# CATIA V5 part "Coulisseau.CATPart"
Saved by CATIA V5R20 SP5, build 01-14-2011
Part number: Coulisseau
Publications: "Longueur coulisseau", "Diamètre coulisseau", "Corps principal"
Bounding box of the stored display mesh (mm): x -5 to 12, y 37.949 to 47.949, z -5 to 16
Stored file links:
  C:\Documents and Settings\pschann\Bureau\IAO\Coulisseau.CATPart
  C:\Documents and Settings\pschann\Bureau\IAO\pschann.CATProduct
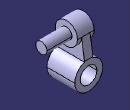
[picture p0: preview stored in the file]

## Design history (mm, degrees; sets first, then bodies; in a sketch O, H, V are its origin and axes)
Parameters
  `Longueur coulisseau` = 10 mm
  `Diamètre coulisseau` = 10 mm
External parameters (linked from other documents)
  `External.Diamètre pivot` = 4 mm
  `External.Epaisseur pivot` = 2 mm
  `External.Longueur axe pivot` = 6 mm
Set1
  Sketch1 on yz-plane, origin (0, 0, 0), H (0, 1, 0), V (0, 0, 1)
    circle A1 centre (42.9491, 12) radius 4
    point P1 (42.9491, 12)
    reference projected point E1 (42.9491, 12) from Point1
    radius A1 = 4 {= `External.Diamètre pivot` /2+`External.Epaisseur pivot`}
    coincidence: P1 E1
Set2
  Point1 "C": linked copy from another document
  Point2 "A": linked copy from another document
  Point3: linked copy from another document
  Line1: linked copy from another document
Body1 (main body)
  Pad1: profile Sketch1, direction (1, 0, 0), length 3 {= `External.Longueur axe pivot` /2}, mirrored extent
  Sketch2 on end face of Pad1, origin (3, 0, 0), H (0, 1, 0), V (0, 0, 1)
    circle A1 centre (42.9491, 12) radius 2
    reference projected point E1 (42.9491, 12) from Point1
    radius A1 = 2 {= `External.Diamètre pivot` /2}
    concentricity: A1 E1
  Pad2: profile Sketch2, direction (1, 0, 0), length 9 {= `External.Longueur axe pivot` *1.5}
  Sketch3 on yz-plane, origin (0, 0, 0), H (0, 1, 0), V (0, 0, 1)
    line L1 (38.9491, 12) -> (37.9491, 5)
    point P1 (38.9491, 12)
    line L2 (37.9491, 5) -> (37.9491, 0)
    line L3 (37.9491, 0) -> (47.9491, 0)
    line L4 (47.9491, 5) -> (47.9491, 0)
    line L5 (47.9491, 5) -> (46.9491, 12)
    point P6 (46.9491, 12)
    line L6 (46.9491, 12) -> (38.9491, 12)
    reference projected point E1 (42.9491, 12) from Point1
    reference projected point E2 (42.9491, 12) from Point1
    reference projected point E3 (42.9491, 12) from Point1
    reference projected line E4 (26.0839, 0) -> (46.0839, 0) from Line1
    distance L2 L4 = 10 {= `Longueur coulisseau`}
    length L6 = 8 {= `External.Diamètre pivot` +`External.Epaisseur pivot` *2}
    length L2 = 5 {= `Diamètre coulisseau` /2}
    length L4 = 5 {= `Diamètre coulisseau` /2}
    vertical: L2 V, L4 V
    horizontal: L3 H, L6 H
    coincidence: L6 E1, L3 E4
    equidistance: L2 L4 E2, P6 P1 E3
  Pad3: profile Sketch3, direction (1, 0, 0), length 1.5 {= `External.Longueur axe pivot` /4}, mirrored extent
  Sketch4 on face of Pad3 from Sketch3.L4, origin (0, 47.9491, 0), H (-1, 0, 0), V (0, 0, 1)
    circle A1 centre (0, 0) radius 5
    reference projected point E1 (0, 0) from Point3
    radius A1 = 5 {= `Diamètre coulisseau` /2}
    concentricity: E1 A1
  Pad4: profile Sketch4, direction (0, -1, 0), length 10 {= `Longueur coulisseau`}
  Sketch5 on face of Pad4, origin (0, 47.9491, 0), H (-1, 0, 0), V (0, 0, 1)
    circle A1 centre (0, 0) radius 3
    reference projected point E1 (0, 0) from Point3
    radius A1 = 3 {= `Diamètre coulisseau` /2-`External.Epaisseur pivot`}
    concentricity: A1 E1
  Pocket1: profile Sketch5, direction (0, -1, 0), through (limit type 6)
